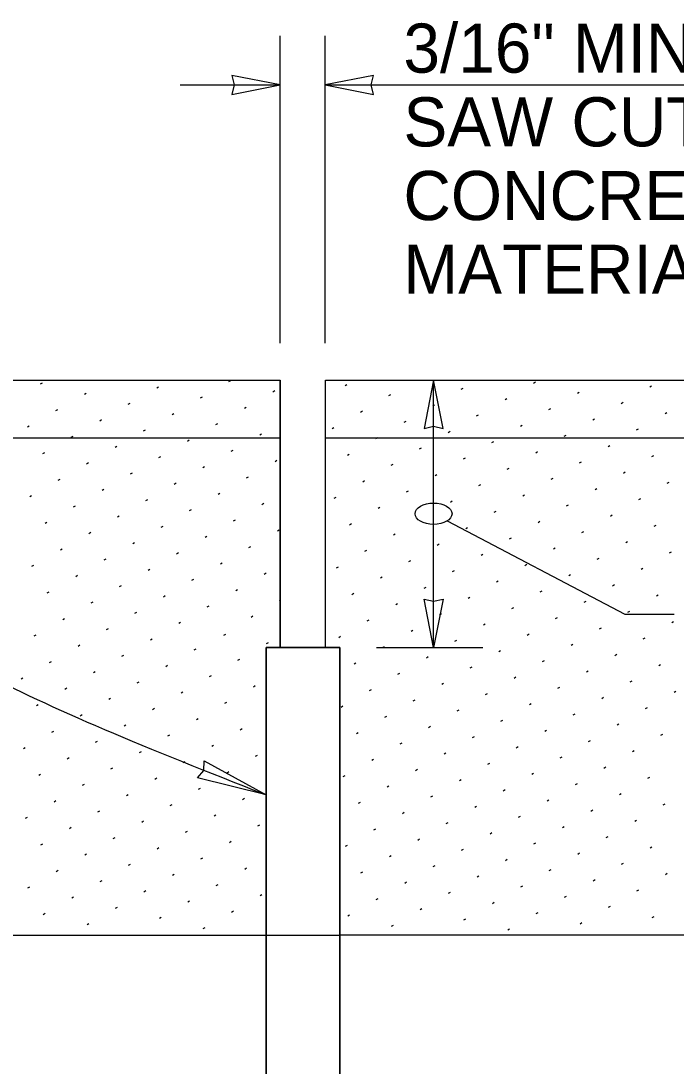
# Model space of a CAD drawing. Extents: x 99862 to 104211, y 98939 to 105076.
# Drawn here: x 101295.5 to 101508.7, y 104040.2 to 104380.5 of the extents above; entities that cross this region are included whole.
import ezdxf

# ---------------------------------------------------------------- set-up
doc = ezdxf.new("R2010")
doc.units = 0
for name, color, linetype in [('Level 1', 7, 'Continuous'), ('Level 14', 7, 'Continuous'), ('Level 15', 7, 'Continuous'), ('Level 2', 7, 'Continuous'), ('Level 20', 7, 'Continuous'), ('Level 3', 7, 'Continuous'), ('Level 6', 7, 'Continuous')]:
    doc.layers.add(name, color=color, linetype=linetype)

msp = doc.modelspace()

# ---------------------------------------------------------------- linework, layer by layer
at = {"layer": 'Level 1'}
for p, q in [((100680.82, 104263.53), (101379.88, 104263.53)), ((101379.88, 104176.51), (101379.88, 104263.53)), ((101379.88, 104263.53), (101379.88, 104176.51)), ((101379.88, 104176.51), (101379.88, 104263.53)), ((101379.88, 104263.53), (101379.88, 104176.51)), ((101379.88, 104263.53), (101379.88, 104176.51)), ((101379.88, 104263.53), (101379.88, 104176.51)), ((101379.88, 104176.51), (101379.88, 104263.53)), ((101394.64, 104176.51), (101394.64, 104263.53)), ((101394.64, 104263.53), (102106.49, 104263.53)), ((101379.88, 104176.51), (101394.64, 104176.51))]:
    msp.add_line(p, q, dxfattribs=at)
at = {"layer": 'Level 14'}
msp.add_lwpolyline([(101375.26, 104176.51), (101399.26, 104176.51), (101399.26, 103945.23), (101375.26, 103945.23)], close=True, dxfattribs=at)
msp.add_lwpolyline([(101399.26, 103945.23), (101399.26, 104176.5), (101375.26, 104176.5), (101375.26, 103945.23), (101399.26, 103945.23)], dxfattribs=at)
at = {"layer": 'Level 15'}
for p, q in [((101379.88, 104275.53), (101379.88, 104375.62)), ((101394.48, 104275.53), (101394.48, 104375.62)), ((101347.3, 104359.62), (101379.88, 104359.62)), ((101394.48, 104359.62), (101680, 104359.62)), ((101429.79, 104176.51), (101429.79, 104263.53)), ((101434.23, 104217.69), (101492.08, 104187.37)), ((101492.08, 104187.37), (101508.08, 104187.37)), ((101411.26, 104176.51), (101445.79, 104176.51))]:
    msp.add_line(p, q, dxfattribs=at)
for points in [[(101379.88, 104359.62), (101364.16, 104362.71), (101364.88, 104359.62), (101364.16, 104356.54)], [(101394.48, 104359.62), (101410.21, 104356.54), (101409.48, 104359.62), (101410.21, 104362.71)], [(101429.79, 104263.53), (101426.71, 104247.81), (101429.79, 104248.53), (101432.88, 104247.81)], [(101429.79, 104176.51), (101426.71, 104192.24), (101429.79, 104191.51), (101432.88, 104192.24)], [(101375.26, 104128.47), (101352.93, 104134.08), (101355.01, 104136.47), (101355.12, 104139.63)]]:
    msp.add_lwpolyline(points, close=True, dxfattribs=at)
msp.add_ellipse((101429.79, 104220.02), major_axis=(-6, 0), ratio=0.57735, dxfattribs=at)
msp.add_open_spline([(101171.95, 104320.66), (101276.02, 104319.89), (101284.33, 104254.26), (101189.41, 104199.91), (101374.66, 104128.72)], degree=2, dxfattribs=at)
at = {"layer": 'Level 2'}
for p, q in [((100862.71, 104082.86), (101375.26, 104082.86)), ((101375.26, 104082.86), (101399.29, 104082.86)), ((101899.72, 104082.86), (101399.29, 104082.86))]:
    msp.add_line(p, q, dxfattribs=at)
at = {"layer": 'Level 3'}
for p, q in [((101363.19, 104263.06), (101363.8, 104263.41)), ((101462.34, 104262.57), (101462.94, 104262.92)), ((101301.86, 104262.29), (101302.46, 104262.64)), ((101339.66, 104261.02), (101340.26, 104261.37)), ((101377.46, 104259.75), (101378.07, 104260.1)), ((101401, 104261.79), (101401.6, 104262.14)), ((101438.8, 104260.53), (101439.41, 104260.88)), ((101476.6, 104259.26), (101477.21, 104259.61)), ((101500.14, 104261.3), (101500.74, 104261.65)), ((101316.12, 104258.98), (101316.73, 104259.33)), ((101353.93, 104257.71), (101354.53, 104258.06)), ((101415.26, 104258.48), (101415.87, 104258.83)), ((101453.07, 104257.22), (101453.67, 104257.57)), ((101490.87, 104255.95), (101491.48, 104256.3)), ((101306.86, 104253.63), (101307.46, 104253.98)), ((101330.39, 104255.67), (101331, 104256.02)), ((101344.66, 104252.36), (101345.26, 104252.71)), ((101368.19, 104254.4), (101368.8, 104254.75)), ((101406, 104253.13), (101406.6, 104253.48)), ((101429.53, 104255.17), (101430.14, 104255.52)), ((101467.34, 104253.91), (101467.94, 104254.26)), ((101505.14, 104252.64), (101505.74, 104252.99)), ((101321.12, 104250.32), (101321.73, 104250.67)), ((101358.93, 104249.05), (101359.53, 104249.4)), ((101420.26, 104249.82), (101420.87, 104250.17)), ((101443.8, 104251.87), (101444.41, 104252.22)), ((101481.6, 104250.6), (101482.21, 104250.95)), ((101297.59, 104248.28), (101298.19, 104248.63)), ((101335.39, 104247.01), (101336, 104247.36)), ((101373.19, 104245.74), (101373.8, 104246.09)), ((101396.73, 104247.78), (101397.34, 104248.13)), ((101434.53, 104246.51), (101435.14, 104246.86)), ((101458.07, 104248.56), (101458.67, 104248.91)), ((101495.87, 104247.29), (101496.48, 104247.64)), ((101311.86, 104244.97), (101312.46, 104245.32)), ((101349.66, 104243.7), (101350.26, 104244.05)), ((101411, 104244.47), (101411.6, 104244.82)), ((101448.8, 104243.21), (101449.41, 104243.56)), ((101472.34, 104245.25), (101472.94, 104245.6)), ((101302.59, 104239.62), (101303.19, 104239.97)), ((101326.12, 104241.66), (101326.73, 104242.01)), ((101363.93, 104240.39), (101364.53, 104240.74)), ((101401.73, 104239.12), (101402.34, 104239.47)), ((101425.26, 104241.16), (101425.87, 104241.51)), ((101463.07, 104239.9), (101463.67, 104240.25)), ((101486.6, 104241.94), (101487.21, 104242.29)), ((101316.86, 104236.31), (101317.46, 104236.66)), ((101340.39, 104238.35), (101341, 104238.7)), ((101378.19, 104237.08), (101378.8, 104237.43)), ((101416, 104235.81), (101416.6, 104236.16)), ((101439.53, 104237.85), (101440.14, 104238.2)), ((101477.34, 104236.59), (101477.94, 104236.94)), ((101500.87, 104238.63), (101501.48, 104238.98)), ((101331.12, 104233), (101331.73, 104233.35)), ((101354.66, 104235.04), (101355.26, 104235.39)), ((101430.26, 104232.5), (101430.87, 104232.85)), ((101453.8, 104234.54), (101454.41, 104234.89)), ((101491.6, 104233.28), (101492.21, 104233.63)), ((101307.59, 104230.96), (101308.19, 104231.31)), ((101345.39, 104229.69), (101346, 104230.04)), ((101368.93, 104231.73), (101369.53, 104232.08)), ((101406.73, 104230.46), (101407.34, 104230.81)), ((101444.53, 104229.19), (101445.14, 104229.54)), ((101468.07, 104231.24), (101468.67, 104231.59)), ((101505.87, 104229.97), (101506.48, 104230.32)), ((101298.32, 104225.61), (101298.93, 104225.96)), ((101321.86, 104227.65), (101322.46, 104228)), ((101359.66, 104226.38), (101360.26, 104226.73)), ((101397.46, 104225.11), (101398.07, 104225.46)), ((101421, 104227.15), (101421.6, 104227.5)), ((101458.8, 104225.88), (101459.41, 104226.23)), ((101482.34, 104227.93), (101482.94, 104228.28)), ((101312.59, 104222.3), (101313.19, 104222.65)), ((101336.12, 104224.34), (101336.73, 104224.69)), ((101373.93, 104223.07), (101374.53, 104223.42)), ((101411.73, 104221.8), (101412.34, 104222.15)), ((101435.26, 104223.84), (101435.87, 104224.19)), ((101473.07, 104222.57), (101473.67, 104222.92)), ((101496.6, 104224.62), (101497.21, 104224.97)), ((101326.86, 104218.99), (101327.46, 104219.34)), ((101350.39, 104221.03), (101351, 104221.38)), ((101449.53, 104220.53), (101450.14, 104220.88)), ((101487.34, 104219.27), (101487.94, 104219.62)), ((101303.32, 104216.95), (101303.93, 104217.3)), ((101341.12, 104215.68), (101341.73, 104216.03)), ((101364.66, 104217.72), (101365.26, 104218.07)), ((101402.46, 104216.45), (101403.07, 104216.8)), ((101440.26, 104215.18), (101440.87, 104215.53)), ((101463.8, 104217.22), (101464.41, 104217.57)), ((101501.6, 104215.96), (101502.21, 104216.31)), ((101317.59, 104213.64), (101318.19, 104213.99)), ((101355.39, 104212.37), (101356, 104212.72)), ((101378.93, 104214.41), (101379.53, 104214.76)), ((101416.73, 104213.14), (101417.34, 104213.49)), ((101454.53, 104211.87), (101455.14, 104212.22)), ((101478.07, 104213.91), (101478.67, 104214.26)), ((101308.32, 104208.29), (101308.93, 104208.64)), ((101331.86, 104210.33), (101332.46, 104210.68)), ((101369.66, 104209.06), (101370.26, 104209.41)), ((101431, 104209.83), (101431.6, 104210.18)), ((101468.8, 104208.56), (101469.41, 104208.91)), ((101492.34, 104210.61), (101492.94, 104210.96)), ((101322.59, 104204.98), (101323.19, 104205.33)), ((101346.12, 104207.02), (101346.73, 104207.37)), ((101407.46, 104207.79), (101408.07, 104208.14)), ((101445.26, 104206.52), (101445.87, 104206.87)), ((101483.07, 104205.25), (101483.67, 104205.6)), ((101506.6, 104207.3), (101507.21, 104207.65)), ((101299.05, 104202.94), (101299.66, 104203.29)), ((101336.86, 104201.67), (101337.46, 104202.02)), ((101360.39, 104203.71), (101361, 104204.06)), ((101398.19, 104202.44), (101398.8, 104202.79)), ((101421.73, 104204.48), (101422.34, 104204.83)), ((101459.53, 104203.21), (101460.14, 104203.56)), ((101497.34, 104201.94), (101497.94, 104202.29)), ((101313.32, 104199.63), (101313.93, 104199.98)), ((101351.12, 104198.36), (101351.73, 104198.71)), ((101374.66, 104200.4), (101375.26, 104200.75)), ((101412.46, 104199.13), (101413.07, 104199.48)), ((101436, 104201.17), (101436.6, 104201.52)), ((101473.8, 104199.9), (101474.41, 104200.25)), ((101327.59, 104196.32), (101328.19, 104196.67)), ((101365.39, 104195.05), (101366, 104195.4)), ((101426.73, 104195.82), (101427.34, 104196.17)), ((101450.26, 104197.86), (101450.87, 104198.21)), ((101464.53, 104194.55), (101465.14, 104194.9)), ((101488.07, 104196.59), (101488.67, 104196.94)), ((101304.05, 104194.28), (101304.66, 104194.63)), ((101341.86, 104193.01), (101342.46, 104193.36)), ((101379.66, 104191.74), (101379.88, 104191.87)), ((101403.19, 104193.78), (101403.8, 104194.13)), ((101441, 104192.51), (101441.6, 104192.86)), ((101478.8, 104191.24), (101479.41, 104191.59)), ((101502.34, 104193.28), (101502.94, 104193.63)), ((101318.32, 104190.97), (101318.93, 104191.32)), ((101356.12, 104189.7), (101356.73, 104190.05)), ((101417.46, 104190.47), (101418.07, 104190.82)), ((101455.26, 104189.2), (101455.87, 104189.55)), ((101493.07, 104187.93), (101493.67, 104188.28)), ((101309.05, 104185.62), (101309.66, 104185.97)), ((101332.59, 104187.66), (101333.19, 104188.01)), ((101346.86, 104184.35), (101347.46, 104184.7)), ((101370.39, 104186.39), (101371, 104186.74)), ((101408.19, 104185.12), (101408.8, 104185.47)), ((101431.73, 104187.16), (101432.34, 104187.51)), ((101469.53, 104185.89), (101470.14, 104186.24)), ((101507.34, 104184.62), (101507.94, 104184.97)), ((101323.32, 104182.31), (101323.93, 104182.66)), ((101422.46, 104181.81), (101423.07, 104182.16)), ((101446, 104183.85), (101446.6, 104184.2)), ((101483.8, 104182.58), (101484.41, 104182.93)), ((101299.78, 104180.27), (101300.39, 104180.62)), ((101337.59, 104179), (101338.19, 104179.35)), ((101361.51, 104180.48), (101362.12, 104180.83)), ((101375.39, 104177.73), (101376, 104178.08)), ((101398.93, 104179.77), (101399.53, 104180.12)), ((101436.73, 104178.5), (101437.34, 104178.85)), ((101460.26, 104180.54), (101460.87, 104180.89)), ((101498.07, 104179.27), (101498.67, 104179.62)), ((101314.05, 104176.96), (101314.66, 104177.31)), ((101351.86, 104175.69), (101352.46, 104176.04)), ((101413.19, 104176.46), (101413.8, 104176.81)), ((101451, 104175.19), (101451.6, 104175.54)), ((101474.53, 104177.23), (101475.14, 104177.58)), ((101304.78, 104171.6), (101305.39, 104171.95)), ((101328.32, 104173.65), (101328.93, 104174)), ((101366.12, 104172.38), (101366.73, 104172.73)), ((101403.93, 104171.11), (101404.53, 104171.46)), ((101427.46, 104173.15), (101428.07, 104173.5)), ((101465.26, 104171.88), (101465.87, 104172.23)), ((101488.8, 104173.92), (101489.41, 104174.27)), ((101319.05, 104168.3), (101319.66, 104168.65)), ((101342.59, 104170.34), (101343.19, 104170.69)), ((101418.19, 104167.8), (101418.8, 104168.15)), ((101441.73, 104169.84), (101442.34, 104170.19)), ((101479.53, 104168.57), (101480.14, 104168.92)), ((101503.07, 104170.61), (101503.67, 104170.96)), ((101295.52, 104166.25), (101296.12, 104166.6)), ((101333.32, 104164.99), (101333.93, 104165.34)), ((101356.86, 104167.03), (101357.46, 104167.38)), ((101432.46, 104164.49), (101433.07, 104164.84)), ((101456, 104166.53), (101456.6, 104166.88)), ((101493.8, 104165.26), (101494.41, 104165.61)), ((101309.78, 104162.94), (101310.39, 104163.29)), ((101347.59, 104161.68), (101348.19, 104162.03)), ((101371.12, 104163.72), (101371.73, 104164.07)), ((101408.93, 104162.45), (101409.53, 104162.8)), ((101446.73, 104161.18), (101447.34, 104161.53)), ((101470.26, 104163.22), (101470.87, 104163.57)), ((101508.07, 104161.95), (101508.67, 104162.3)), ((101300.52, 104157.59), (101301.12, 104157.94)), ((101324.05, 104159.63), (101324.66, 104159.98)), ((101361.86, 104158.37), (101362.46, 104158.72)), ((101399.66, 104157.1), (101400.26, 104157.45)), ((101423.19, 104159.14), (101423.8, 104159.49)), ((101461, 104157.87), (101461.6, 104158.22)), ((101484.53, 104159.91), (101485.14, 104160.26)), ((101314.78, 104154.28), (101315.39, 104154.63)), ((101338.32, 104156.33), (101338.93, 104156.68)), ((101413.93, 104153.79), (101414.53, 104154.14)), ((101437.46, 104155.83), (101438.07, 104156.18)), ((101475.26, 104154.56), (101475.87, 104154.91)), ((101498.8, 104156.6), (101499.41, 104156.95)), ((101329.05, 104150.97), (101329.66, 104151.32)), ((101352.59, 104153.02), (101353.19, 104153.37)), ((101428.19, 104150.48), (101428.8, 104150.83)), ((101451.73, 104152.52), (101452.34, 104152.87)), ((101489.53, 104151.25), (101490.14, 104151.6)), ((101305.52, 104148.93), (101306.12, 104149.28)), ((101343.32, 104147.67), (101343.93, 104148.02)), ((101366.86, 104149.71), (101367.46, 104150.06)), ((101404.66, 104148.44), (101405.26, 104148.79)), ((101442.46, 104147.17), (101443.07, 104147.52)), ((101466, 104149.21), (101466.6, 104149.56)), ((101503.8, 104147.94), (101504.41, 104148.29)), ((101296.25, 104143.58), (101296.86, 104143.93)), ((101319.78, 104145.62), (101320.39, 104145.97)), ((101357.59, 104144.36), (101358.19, 104144.71)), ((101418.93, 104145.13), (101419.53, 104145.48)), ((101456.73, 104143.86), (101457.34, 104144.21)), ((101480.26, 104145.9), (101480.87, 104146.25)), ((101310.52, 104140.27), (101311.12, 104140.62)), ((101334.05, 104142.31), (101334.66, 104142.66)), ((101371.86, 104141.05), (101372.46, 104141.4)), ((101433.19, 104141.82), (101433.8, 104142.17)), ((101471, 104140.55), (101471.6, 104140.9)), ((101494.53, 104142.59), (101495.14, 104142.94)), ((101324.78, 104136.96), (101325.39, 104137.31)), ((101348.32, 104139), (101348.93, 104139.35)), ((101409.66, 104139.78), (101410.26, 104140.13)), ((101447.46, 104138.51), (101448.07, 104138.86)), ((101485.26, 104137.24), (101485.87, 104137.59)), ((101301.25, 104134.92), (101301.86, 104135.27)), ((101339.05, 104133.65), (101339.66, 104134)), ((101362.59, 104135.7), (101363.19, 104136.05)), ((101400.39, 104134.43), (101401, 104134.78)), ((101423.93, 104136.47), (101424.53, 104136.82)), ((101461.73, 104135.2), (101462.34, 104135.55)), ((101499.53, 104133.93), (101500.14, 104134.28)), ((101315.52, 104131.61), (101316.12, 104131.96)), ((101353.32, 104130.34), (101353.93, 104130.69)), ((101414.66, 104131.12), (101415.26, 104131.47)), ((101438.19, 104133.16), (101438.8, 104133.51)), ((101452.46, 104129.85), (101453.07, 104130.2)), ((101476, 104131.89), (101476.6, 104132.24)), ((101329.78, 104128.3), (101330.39, 104128.65)), ((101367.59, 104127.04), (101368.19, 104127.39)), ((101428.93, 104127.81), (101429.53, 104128.16)), ((101466.73, 104126.54), (101467.34, 104126.89)), ((101490.26, 104128.58), (101490.87, 104128.93)), ((101306.25, 104126.26), (101306.86, 104126.61)), ((101344.05, 104124.99), (101344.66, 104125.34)), ((101405.39, 104125.77), (101406, 104126.12)), ((101443.19, 104124.5), (101443.8, 104124.85)), ((101481, 104123.23), (101481.6, 104123.58)), ((101504.53, 104125.27), (101505.14, 104125.62)), ((101296.98, 104120.91), (101297.59, 104121.26)), ((101320.52, 104122.95), (101321.12, 104123.3)), ((101334.78, 104119.64), (101335.39, 104119.99)), ((101358.32, 104121.68), (101358.93, 104122.03)), ((101419.66, 104122.46), (101420.26, 104122.81)), ((101457.46, 104121.19), (101458.07, 104121.54)), ((101495.26, 104119.92), (101495.87, 104120.27)), ((101311.25, 104117.6), (101311.86, 104117.95)), ((101349.05, 104116.33), (101349.66, 104116.68)), ((101372.59, 104118.37), (101373.19, 104118.72)), ((101410.39, 104117.11), (101411, 104117.46)), ((101433.93, 104119.15), (101434.53, 104119.5)), ((101471.73, 104117.88), (101472.34, 104118.23)), ((101325.52, 104114.29), (101326.12, 104114.64)), ((101363.32, 104113.02), (101363.93, 104113.37)), ((101424.66, 104113.8), (101425.26, 104114.15)), ((101448.19, 104115.84), (101448.8, 104116.19)), ((101486, 104114.57), (101486.6, 104114.92)), ((101301.98, 104112.25), (101302.59, 104112.6)), ((101339.78, 104110.98), (101340.39, 104111.33)), ((101401.12, 104111.76), (101401.73, 104112.11)), ((101438.93, 104110.49), (101439.53, 104110.84)), ((101462.46, 104112.53), (101463.07, 104112.88)), ((101500.26, 104111.26), (101500.87, 104111.61)), ((101316.25, 104108.94), (101316.86, 104109.29)), ((101354.05, 104107.67), (101354.66, 104108.02)), ((101415.39, 104108.45), (101416, 104108.8)), ((101453.19, 104107.18), (101453.8, 104107.53)), ((101476.73, 104109.22), (101477.34, 104109.57)), ((101306.98, 104103.59), (101307.59, 104103.94)), ((101330.52, 104105.63), (101331.12, 104105.98)), ((101368.32, 104104.36), (101368.93, 104104.71)), ((101406.12, 104103.1), (101406.73, 104103.45)), ((101429.66, 104105.14), (101430.26, 104105.49)), ((101467.46, 104103.87), (101468.07, 104104.22)), ((101491, 104105.91), (101491.6, 104106.26)), ((101321.25, 104100.28), (101321.86, 104100.63)), ((101344.78, 104102.32), (101345.39, 104102.67)), ((101420.39, 104099.79), (101421, 104100.14)), ((101443.93, 104101.83), (101444.53, 104102.18)), ((101481.73, 104100.56), (101482.34, 104100.91)), ((101505.26, 104102.6), (101505.87, 104102.95)), ((101297.71, 104098.24), (101298.32, 104098.59)), ((101335.52, 104096.97), (101336.12, 104097.32)), ((101359.05, 104099.01), (101359.66, 104099.36)), ((101434.66, 104096.48), (101435.26, 104096.83)), ((101458.19, 104098.52), (101458.8, 104098.87)), ((101496, 104097.25), (101496.6, 104097.6)), ((101311.98, 104094.93), (101312.59, 104095.28)), ((101349.78, 104093.66), (101350.39, 104094.01)), ((101373.32, 104095.7), (101373.93, 104096.05)), ((101411.12, 104094.44), (101411.73, 104094.79)), ((101448.93, 104093.17), (101449.53, 104093.52)), ((101472.46, 104095.21), (101473.07, 104095.56)), ((101302.71, 104089.58), (101303.32, 104089.93)), ((101326.25, 104091.62), (101326.86, 104091.97)), ((101364.05, 104090.35), (101364.66, 104090.7)), ((101401.86, 104089.08), (101402.46, 104089.43)), ((101425.39, 104091.13), (101426, 104091.48)), ((101463.19, 104089.86), (101463.8, 104090.21)), ((101486.73, 104091.9), (101487.34, 104092.25)), ((101316.98, 104086.27), (101317.59, 104086.62)), ((101340.52, 104088.31), (101341.12, 104088.66)), ((101416.12, 104085.77), (101416.73, 104086.12)), ((101439.66, 104087.82), (101440.26, 104088.17)), ((101477.46, 104086.55), (101478.07, 104086.9)), ((101501, 104088.59), (101501.6, 104088.94)), ((101354.78, 104085), (101355.39, 104085.35)), ((101453.93, 104084.51), (101454.53, 104084.86))]:
    msp.add_line(p, q, dxfattribs=at)
at = {"layer": 'Level 6'}
for p, q in [((101379.88, 104244.65), (100169.63, 104244.65)), ((102647.84, 104244.65), (101394.64, 104244.65))]:
    msp.add_line(p, q, dxfattribs=at)

# ---------------------------------------------------------------- texts
at = {"layer": 'Level 20'}
for s, p in [('3/16" MIN. TO 5/16" MAX. ', (101419.98, 104363.62)), ('SAW CUT AFTER ', (101419.98, 104339.62)), ('CONCRETE PATCH ', (101419.98, 104315.62)), ('MATERIAL HAS SET', (101419.98, 104291.62))]:
    msp.add_text(s, height=16, dxfattribs=at).set_placement(p)

doc.saveas('drawing.dxf')
